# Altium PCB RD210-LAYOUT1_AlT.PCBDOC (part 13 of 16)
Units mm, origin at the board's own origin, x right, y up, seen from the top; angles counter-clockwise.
Board outline 330 x 300 mm, 6 copper layers (TOP, Mid-Layer 1, Mid-Layer 2, Mid-Layer 3, Mid-Layer 4, BOTTOM), stack 1.422 mm thick; 981 components, 463 nets, 2326 pads, 12534 vias.
Unrouted connection lines stored in the file: 6.
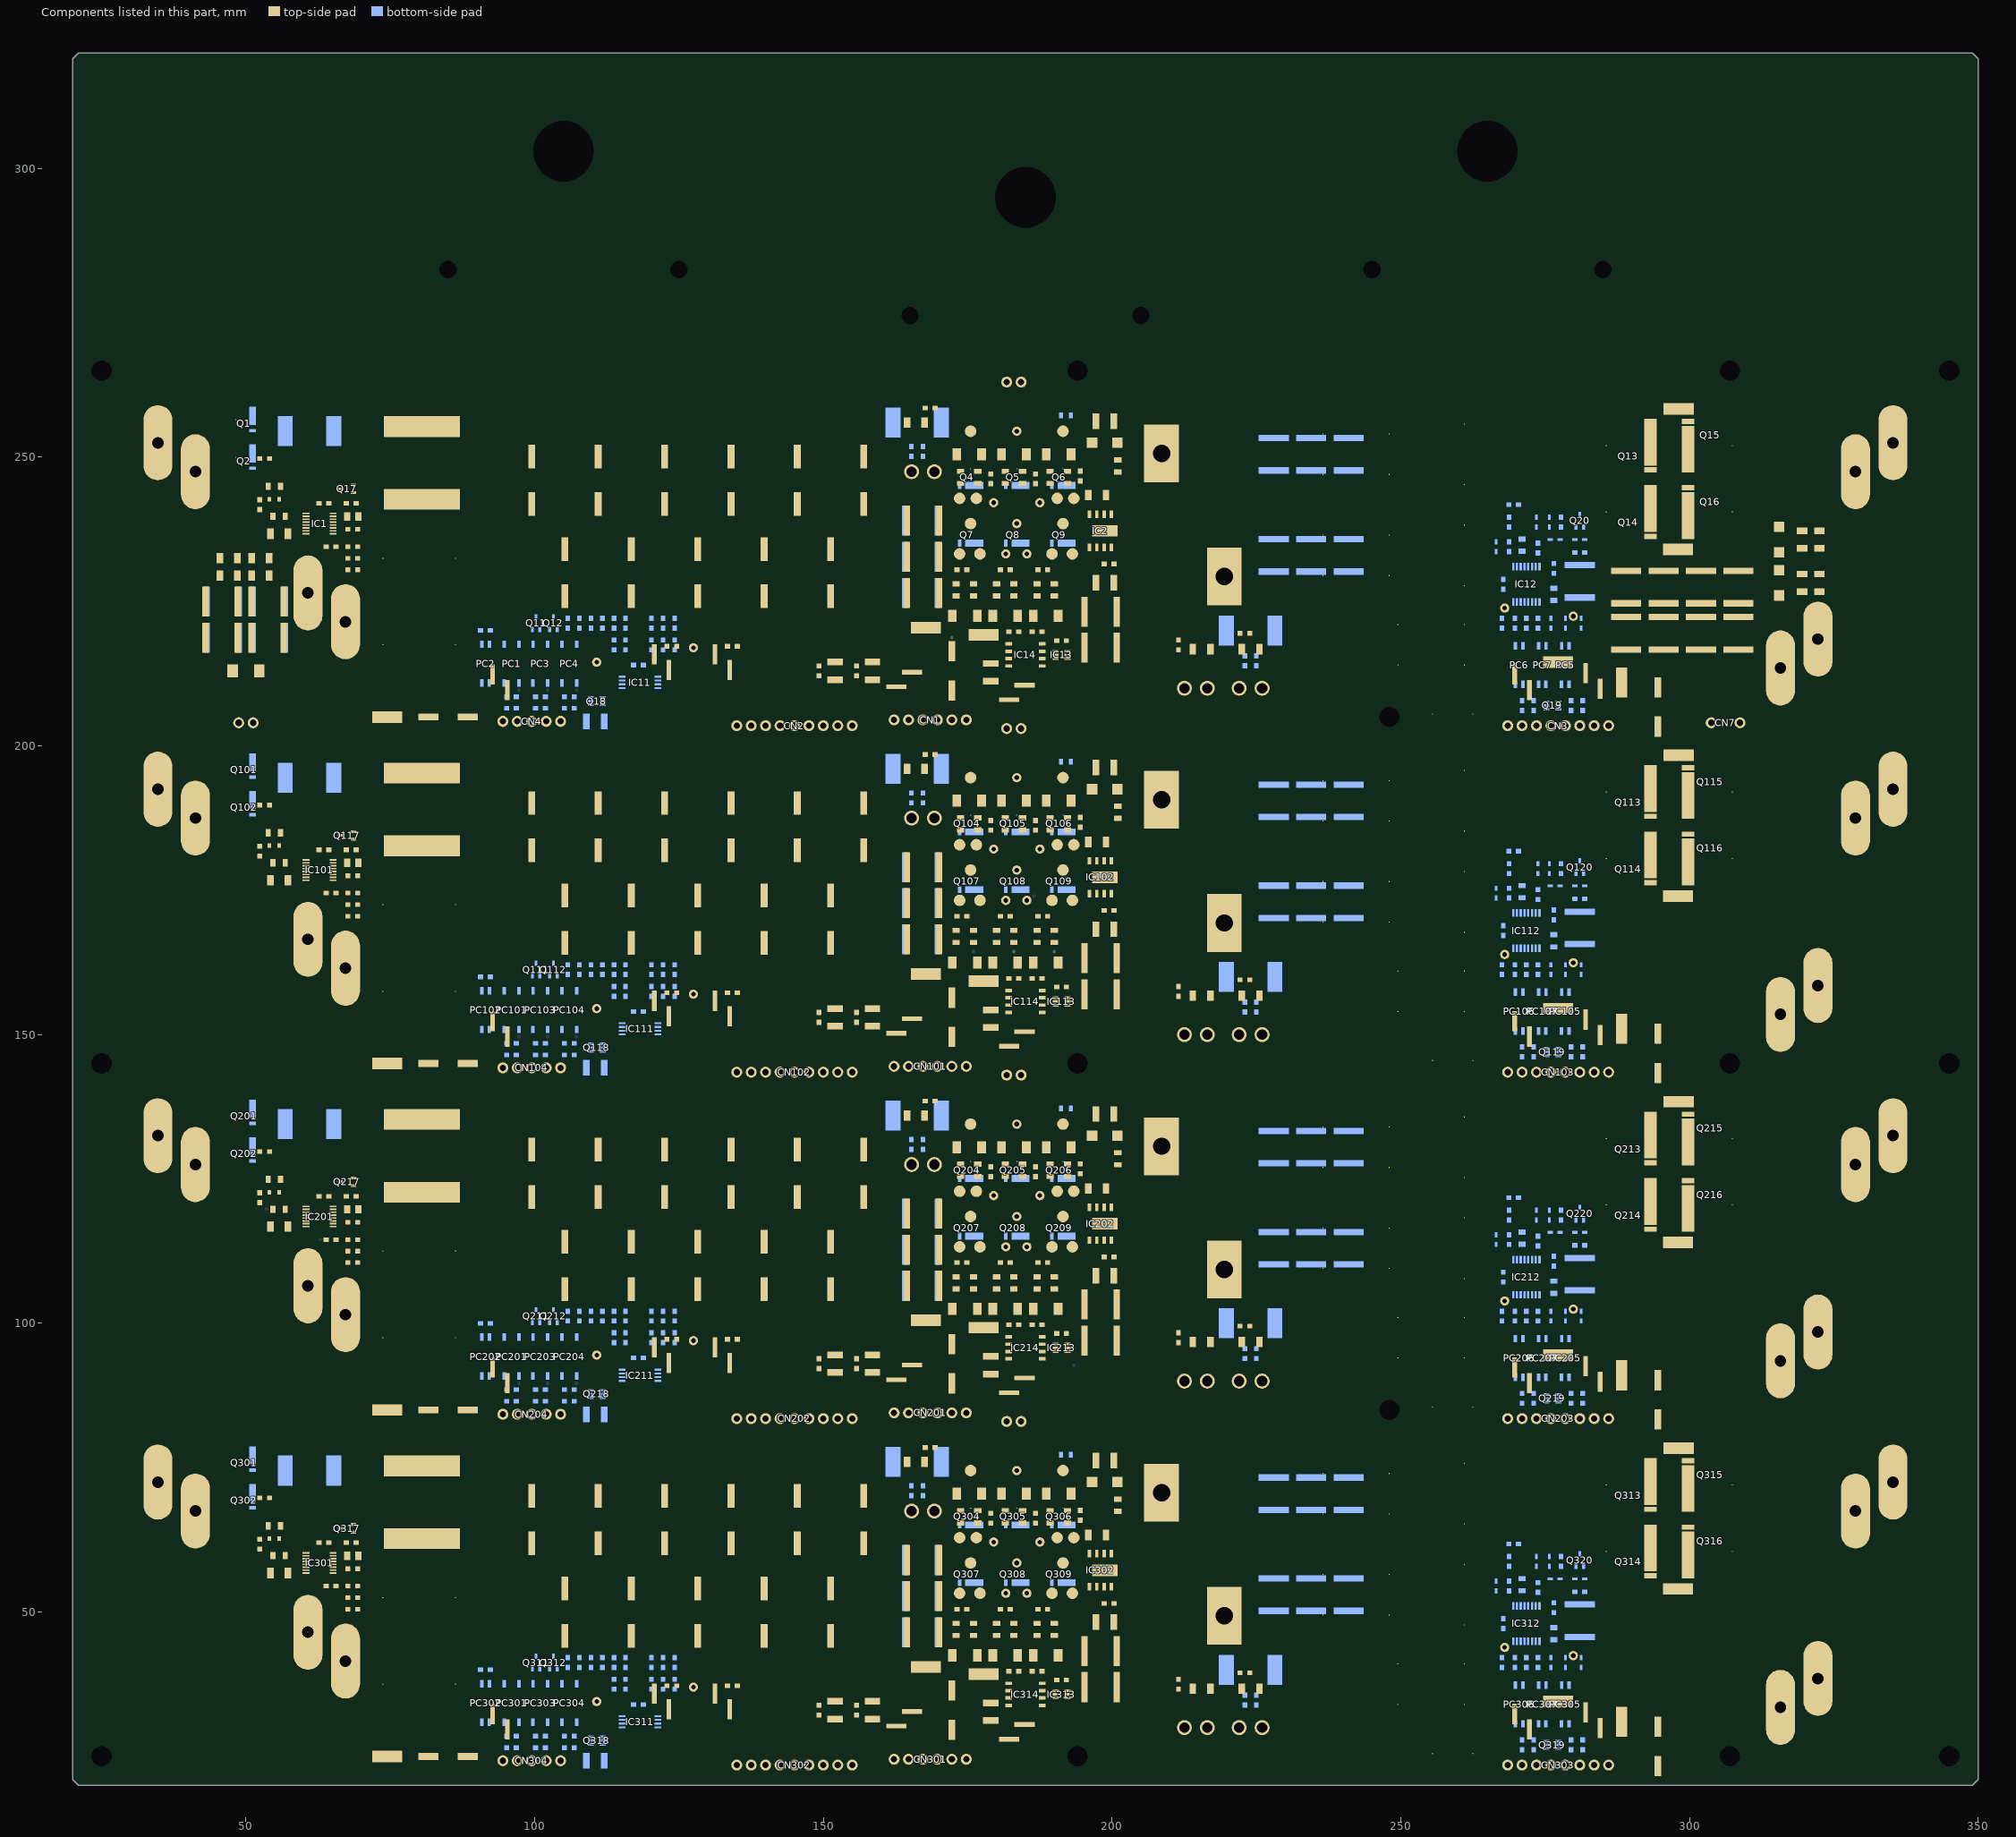
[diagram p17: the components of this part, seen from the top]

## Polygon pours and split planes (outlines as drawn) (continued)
no net on Top Overlay "TOPOVERLAY427" (solid, pour order 0): 191.7,248.8 191.7,252.2 192.65,252.2 192.65,251.7 192,251.7 192,249.3 192.65,249.3 192.65,248.8
no net on Top Overlay "TOPOVERLAY428" (solid, pour order 0): 189.45,220.8 189.45,224.2 190.4,224.2 190.4,223.7 189.75,223.7 189.75,221.3 190.4,221.3 190.4,220.8
no net on Top Overlay "TOPOVERLAY429" (solid, pour order 0): 59.1,241 ccw(c59.4,241) 59.7,241 ccw(c59.4,241)
no net on Top Overlay "TOPOVERLAY430" (solid, pour order 0): 100.325,182.15 102.69,182.15 cw(c99.5,186) 100.325,181.069
no net on Top Overlay "TOPOVERLAY431" (solid, pour order 0): 98.675,181.069 cw(c99.5,186) 96.31,182.15 98.675,182.15
no net on Top Overlay "TOPOVERLAY432" (solid, pour order 0): 111.825,182.15 114.19,182.15 cw(c111,186) 111.825,181.069
no net on Top Overlay "TOPOVERLAY433" (solid, pour order 0): 110.175,181.069 cw(c111,186) 107.81,182.15 110.175,182.15
no net on Top Overlay "TOPOVERLAY434" (solid, pour order 0): 123.325,182.15 125.69,182.15 cw(c122.5,186) 123.325,181.069
no net on Top Overlay "TOPOVERLAY435" (solid, pour order 0): 121.675,181.069 cw(c122.5,186) 119.31,182.15 121.675,182.15
no net on Top Overlay "TOPOVERLAY436" (solid, pour order 0): 134.825,182.15 137.19,182.15 cw(c134,186) 134.825,181.069
no net on Top Overlay "TOPOVERLAY437" (solid, pour order 0): 133.175,181.069 cw(c134,186) 130.81,182.15 133.175,182.15
no net on Top Overlay "TOPOVERLAY438" (solid, pour order 0): 146.325,182.15 148.69,182.15 cw(c145.5,186) 146.325,181.069
no net on Top Overlay "TOPOVERLAY439" (solid, pour order 0): 144.675,181.069 cw(c145.5,186) 142.31,182.15 144.675,182.15
no net on Top Overlay "TOPOVERLAY440" (solid, pour order 0): 157.825,182.15 160.19,182.15 cw(c157,186) 157.825,181.069
no net on Top Overlay "TOPOVERLAY441" (solid, pour order 0): 156.175,181.069 cw(c157,186) 153.81,182.15 156.175,182.15
no net on Top Overlay "TOPOVERLAY442" (solid, pour order 0): 148.06,173.85 cw(c151.25,170) 150.425,174.931 150.425,173.85
no net on Top Overlay "TOPOVERLAY443" (solid, pour order 0): 152.075,173.85 152.075,174.931 cw(c151.25,170) 154.44,173.85
no net on Top Overlay "TOPOVERLAY444" (solid, pour order 0): 136.56,173.85 cw(c139.75,170) 138.925,174.931 138.925,173.85
no net on Top Overlay "TOPOVERLAY445" (solid, pour order 0): 140.575,173.85 140.575,174.931 cw(c139.75,170) 142.94,173.85
no net on Top Overlay "TOPOVERLAY446" (solid, pour order 0): 125.06,173.85 cw(c128.25,170) 127.425,174.931 127.425,173.85
no net on Top Overlay "TOPOVERLAY447" (solid, pour order 0): 129.075,173.85 129.075,174.931 cw(c128.25,170) 131.44,173.85
no net on Top Overlay "TOPOVERLAY448" (solid, pour order 0): 113.56,173.85 cw(c116.75,170) 115.925,174.931 115.925,173.85
no net on Top Overlay "TOPOVERLAY449" (solid, pour order 0): 117.575,173.85 117.575,174.931 cw(c116.75,170) 119.94,173.85
no net on Top Overlay "TOPOVERLAY450" (solid, pour order 0): 102.06,173.85 cw(c105.25,170) 104.425,174.931 104.425,173.85
no net on Top Overlay "TOPOVERLAY451" (solid, pour order 0): 106.075,173.85 106.075,174.931 cw(c105.25,170) 108.44,173.85
no net on Top Overlay "TOPOVERLAY452" (solid, pour order 0): 100.325,122.15 102.69,122.15 cw(c99.5,126) 100.325,121.069
no net on Top Overlay "TOPOVERLAY453" (solid, pour order 0): 98.675,121.069 cw(c99.5,126) 96.31,122.15 98.675,122.15
no net on Top Overlay "TOPOVERLAY454" (solid, pour order 0): 111.825,122.15 114.19,122.15 cw(c111,126) 111.825,121.069
no net on Top Overlay "TOPOVERLAY455" (solid, pour order 0): 110.175,121.069 cw(c111,126) 107.81,122.15 110.175,122.15
no net on Top Overlay "TOPOVERLAY456" (solid, pour order 0): 123.325,122.15 125.69,122.15 cw(c122.5,126) 123.325,121.069
no net on Top Overlay "TOPOVERLAY457" (solid, pour order 0): 121.675,121.069 cw(c122.5,126) 119.31,122.15 121.675,122.15
no net on Top Overlay "TOPOVERLAY458" (solid, pour order 0): 134.825,122.15 137.19,122.15 cw(c134,126) 134.825,121.069
no net on Top Overlay "TOPOVERLAY459" (solid, pour order 0): 133.175,121.069 cw(c134,126) 130.81,122.15 133.175,122.15
no net on Top Overlay "TOPOVERLAY460" (solid, pour order 0): 146.325,122.15 148.69,122.15 cw(c145.5,126) 146.325,121.069
no net on Top Overlay "TOPOVERLAY461" (solid, pour order 0): 144.675,121.069 cw(c145.5,126) 142.31,122.15 144.675,122.15
no net on Top Overlay "TOPOVERLAY462" (solid, pour order 0): 157.825,122.15 160.19,122.15 cw(c157,126) 157.825,121.069
no net on Top Overlay "TOPOVERLAY463" (solid, pour order 0): 156.175,121.069 cw(c157,126) 153.81,122.15 156.175,122.15
no net on Top Overlay "TOPOVERLAY464" (solid, pour order 0): 148.06,113.85 cw(c151.25,110) 150.425,114.931 150.425,113.85
no net on Top Overlay "TOPOVERLAY465" (solid, pour order 0): 152.075,113.85 152.075,114.931 cw(c151.25,110) 154.44,113.85
no net on Top Overlay "TOPOVERLAY466" (solid, pour order 0): 136.56,113.85 cw(c139.75,110) 138.925,114.931 138.925,113.85
no net on Top Overlay "TOPOVERLAY467" (solid, pour order 0): 140.575,113.85 140.575,114.931 cw(c139.75,110) 142.94,113.85
no net on Top Overlay "TOPOVERLAY468" (solid, pour order 0): 125.06,113.85 cw(c128.25,110) 127.425,114.931 127.425,113.85
no net on Top Overlay "TOPOVERLAY469" (solid, pour order 0): 129.075,113.85 129.075,114.931 cw(c128.25,110) 131.44,113.85
no net on Top Overlay "TOPOVERLAY470" (solid, pour order 0): 113.56,113.85 cw(c116.75,110) 115.925,114.931 115.925,113.85
no net on Top Overlay "TOPOVERLAY471" (solid, pour order 0): 117.575,113.85 117.575,114.931 cw(c116.75,110) 119.94,113.85
no net on Top Overlay "TOPOVERLAY472" (solid, pour order 0): 102.06,113.85 cw(c105.25,110) 104.425,114.931 104.425,113.85
no net on Top Overlay "TOPOVERLAY473" (solid, pour order 0): 106.075,113.85 106.075,114.931 cw(c105.25,110) 108.44,113.85
no net on Top Overlay "TOPOVERLAY474" (solid, pour order 0): 100.325,62.15 102.69,62.15 cw(c99.5,66) 100.325,61.069
no net on Top Overlay "TOPOVERLAY475" (solid, pour order 0): 98.675,61.069 cw(c99.5,66) 96.31,62.15 98.675,62.15
no net on Top Overlay "TOPOVERLAY476" (solid, pour order 0): 111.825,62.15 114.19,62.15 cw(c111,66) 111.825,61.069
no net on Top Overlay "TOPOVERLAY477" (solid, pour order 0): 110.175,61.069 cw(c111,66) 107.81,62.15 110.175,62.15
no net on Top Overlay "TOPOVERLAY478" (solid, pour order 0): 123.325,62.15 125.69,62.15 cw(c122.5,66) 123.325,61.069
no net on Top Overlay "TOPOVERLAY479" (solid, pour order 0): 121.675,61.069 cw(c122.5,66) 119.31,62.15 121.675,62.15
no net on Top Overlay "TOPOVERLAY480" (solid, pour order 0): 134.825,62.15 137.19,62.15 cw(c134,66) 134.825,61.069
no net on Top Overlay "TOPOVERLAY481" (solid, pour order 0): 133.175,61.069 cw(c134,66) 130.81,62.15 133.175,62.15
no net on Top Overlay "TOPOVERLAY482" (solid, pour order 0): 146.325,62.15 148.69,62.15 cw(c145.5,66) 146.325,61.069
no net on Top Overlay "TOPOVERLAY483" (solid, pour order 0): 144.675,61.069 cw(c145.5,66) 142.31,62.15 144.675,62.15
no net on Top Overlay "TOPOVERLAY484" (solid, pour order 0): 157.825,62.15 160.19,62.15 cw(c157,66) 157.825,61.069
no net on Top Overlay "TOPOVERLAY485" (solid, pour order 0): 156.175,61.069 cw(c157,66) 153.81,62.15 156.175,62.15
no net on Top Overlay "TOPOVERLAY486" (solid, pour order 0): 148.06,53.85 cw(c151.25,50) 150.425,54.931 150.425,53.85
no net on Top Overlay "TOPOVERLAY487" (solid, pour order 0): 152.075,53.85 152.075,54.931 cw(c151.25,50) 154.44,53.85
no net on Top Overlay "TOPOVERLAY488" (solid, pour order 0): 136.56,53.85 cw(c139.75,50) 138.925,54.931 138.925,53.85
no net on Top Overlay "TOPOVERLAY489" (solid, pour order 0): 140.575,53.85 140.575,54.931 cw(c139.75,50) 142.94,53.85
no net on Top Overlay "TOPOVERLAY490" (solid, pour order 0): 125.06,53.85 cw(c128.25,50) 127.425,54.931 127.425,53.85
no net on Top Overlay "TOPOVERLAY491" (solid, pour order 0): 129.075,53.85 129.075,54.931 cw(c128.25,50) 131.44,53.85
no net on Top Overlay "TOPOVERLAY492" (solid, pour order 0): 113.56,53.85 cw(c116.75,50) 115.925,54.931 115.925,53.85
no net on Top Overlay "TOPOVERLAY493" (solid, pour order 0): 117.575,53.85 117.575,54.931 cw(c116.75,50) 119.94,53.85
no net on Top Overlay "TOPOVERLAY494" (solid, pour order 0): 102.06,53.85 cw(c105.25,50) 104.425,54.931 104.425,53.85
no net on Top Overlay "TOPOVERLAY495" (solid, pour order 0): 106.075,53.85 106.075,54.931 cw(c105.25,50) 108.44,53.85
no net on Top Overlay "TOPOVERLAY496" (solid, pour order 0): 154.75,140.675 ccw(c155,140.675) 155.25,140.675 ccw(c155,140.675)
no net on Top Overlay "TOPOVERLAY497" (solid, pour order 0): 154.75,80.675 ccw(c155,80.675) 155.25,80.675 ccw(c155,80.675)
no net on Top Overlay "TOPOVERLAY498" (solid, pour order 0): 154.75,20.675 ccw(c155,20.675) 155.25,20.675 ccw(c155,20.675)
no net on Top Overlay "TOPOVERLAY499" (solid, pour order 0): 176.2,188.8 176.2,192.2 177.15,192.2 177.15,191.7 176.5,191.7 176.5,189.3 177.15,189.3 177.15,188.8
no net on Top Overlay "TOPOVERLAY500" (solid, pour order 0): 183.95,188.8 183.95,192.2 184.9,192.2 184.9,191.7 184.25,191.7 184.25,189.3 184.9,189.3 184.9,188.8
no net on Top Overlay "TOPOVERLAY501" (solid, pour order 0): 191.7,188.8 191.7,192.2 192.65,192.2 192.65,191.7 192,191.7 192,189.3 192.65,189.3 192.65,188.8
no net on Top Overlay "TOPOVERLAY502" (solid, pour order 0): 175.45,160.8 175.45,164.2 176.4,164.2 176.4,163.7 175.75,163.7 175.75,161.3 176.4,161.3 176.4,160.8
no net on Top Overlay "TOPOVERLAY503" (solid, pour order 0): 182.45,160.8 182.45,164.2 183.4,164.2 183.4,163.7 182.75,163.7 182.75,161.3 183.4,161.3 183.4,160.8
no net on Top Overlay "TOPOVERLAY504" (solid, pour order 0): 189.45,160.8 189.45,164.2 190.4,164.2 190.4,163.7 189.75,163.7 189.75,161.3 190.4,161.3 190.4,160.8
no net on Top Overlay "TOPOVERLAY505" (solid, pour order 0): 176.2,128.8 176.2,132.2 177.15,132.2 177.15,131.7 176.5,131.7 176.5,129.3 177.15,129.3 177.15,128.8
no net on Top Overlay "TOPOVERLAY506" (solid, pour order 0): 183.95,128.8 183.95,132.2 184.9,132.2 184.9,131.7 184.25,131.7 184.25,129.3 184.9,129.3 184.9,128.8
no net on Top Overlay "TOPOVERLAY507" (solid, pour order 0): 191.7,128.8 191.7,132.2 192.65,132.2 192.65,131.7 192,131.7 192,129.3 192.65,129.3 192.65,128.8
no net on Top Overlay "TOPOVERLAY508" (solid, pour order 0): 175.45,100.8 175.45,104.2 176.4,104.2 176.4,103.7 175.75,103.7 175.75,101.3 176.4,101.3 176.4,100.8
no net on Top Overlay "TOPOVERLAY509" (solid, pour order 0): 182.45,100.8 182.45,104.2 183.4,104.2 183.4,103.7 182.75,103.7 182.75,101.3 183.4,101.3 183.4,100.8
no net on Top Overlay "TOPOVERLAY510" (solid, pour order 0): 189.45,100.8 189.45,104.2 190.4,104.2 190.4,103.7 189.75,103.7 189.75,101.3 190.4,101.3 190.4,100.8
no net on Top Overlay "TOPOVERLAY511" (solid, pour order 0): 176.2,68.8 176.2,72.2 177.15,72.2 177.15,71.7 176.5,71.7 176.5,69.3 177.15,69.3 177.15,68.8
no net on Top Overlay "TOPOVERLAY512" (solid, pour order 0): 183.95,68.8 183.95,72.2 184.9,72.2 184.9,71.7 184.25,71.7 184.25,69.3 184.9,69.3 184.9,68.8
no net on Top Overlay "TOPOVERLAY513" (solid, pour order 0): 191.7,68.8 191.7,72.2 192.65,72.2 192.65,71.7 192,71.7 192,69.3 192.65,69.3 192.65,68.8
no net on Top Overlay "TOPOVERLAY514" (solid, pour order 0): 175.45,40.8 175.45,44.2 176.4,44.2 176.4,43.7 175.75,43.7 175.75,41.3 176.4,41.3 176.4,40.8
no net on Top Overlay "TOPOVERLAY515" (solid, pour order 0): 182.45,40.8 182.45,44.2 183.4,44.2 183.4,43.7 182.75,43.7 182.75,41.3 183.4,41.3 183.4,40.8
no net on Top Overlay "TOPOVERLAY516" (solid, pour order 0): 189.45,40.8 189.45,44.2 190.4,44.2 190.4,43.7 189.75,43.7 189.75,41.3 190.4,41.3 190.4,40.8
no net on Top Overlay "TOPOVERLAY517" (solid, pour order 0): 59.1,180.7 ccw(c59.4,180.7) 59.7,180.7 ccw(c59.4,180.7)
no net on Top Overlay "TOPOVERLAY518" (solid, pour order 0): 59.1,120.7 ccw(c59.4,120.7) 59.7,120.7 ccw(c59.4,120.7)
no net on Top Overlay "TOPOVERLAY519" (solid, pour order 0): 59.1,60.7 ccw(c59.4,60.7) 59.7,60.7 ccw(c59.4,60.7)
no net on Top Overlay "TOPOVERLAY520" (solid, pour order 0): 51,201.15 ccw(c51.25,201.15) 51.5,201.15 ccw(c51.25,201.15)
no net on Top Overlay "TOPOVERLAY521" (solid, pour order 0): 188.95,216.4 ccw(c189.2,216.4) 189.45,216.4 ccw(c189.2,216.4)
no net on Top Overlay "TOPOVERLAY522" (solid, pour order 0): 180.75,217.655 ccw(c181,217.655) 181.25,217.655 ccw(c181,217.655)
no net on Top Overlay "TOPOVERLAY523" (solid, pour order 0): 188.95,156.4 ccw(c189.2,156.4) 189.45,156.4 ccw(c189.2,156.4)
no net on Top Overlay "TOPOVERLAY524" (solid, pour order 0): 180.75,157.655 ccw(c181,157.655) 181.25,157.655 ccw(c181,157.655)
no net on Top Overlay "TOPOVERLAY525" (solid, pour order 0): 188.95,96.4 ccw(c189.2,96.4) 189.45,96.4 ccw(c189.2,96.4)
no net on Top Overlay "TOPOVERLAY526" (solid, pour order 0): 180.75,97.655 ccw(c181,97.655) 181.25,97.655 ccw(c181,97.655)
no net on Top Overlay "TOPOVERLAY527" (solid, pour order 0): 188.95,36.4 ccw(c189.2,36.4) 189.45,36.4 ccw(c189.2,36.4)
no net on Top Overlay "TOPOVERLAY528" (solid, pour order 0): 180.75,37.655 ccw(c181,37.655) 181.25,37.655 ccw(c181,37.655)
no net on Top Overlay "TOPOVERLAY529" (solid, pour order 0): 69.3,243.85 ccw(c69.55,243.85) 69.8,243.85 ccw(c69.55,243.85)
no net on Top Overlay "TOPOVERLAY530" (solid, pour order 0): 69.3,183.85 ccw(c69.55,183.85) 69.8,183.85 ccw(c69.55,183.85)
no net on Top Overlay "TOPOVERLAY531" (solid, pour order 0): 69.3,123.85 ccw(c69.55,123.85) 69.8,123.85 ccw(c69.55,123.85)
no net on Top Overlay "TOPOVERLAY532" (solid, pour order 0): 69.3,63.85 ccw(c69.55,63.85) 69.8,63.85 ccw(c69.55,63.85)
no net on Top Overlay "TOPOVERLAY533" (solid, pour order 0): 94.25,27.1 ccw(c94.5,27.1) 94.75,27.1 ccw(c94.5,27.1)
no net on Top Overlay "TOPOVERLAY534" (solid, pour order 0): 94.25,207.1 ccw(c94.5,207.1) 94.75,207.1 ccw(c94.5,207.1)
no net on Top Overlay "TOPOVERLAY535" (solid, pour order 0): 94.25,147.1 ccw(c94.5,147.1) 94.75,147.1 ccw(c94.5,147.1)
no net on Top Overlay "TOPOVERLAY536" (solid, pour order 0): 94.25,87.1 ccw(c94.5,87.1) 94.75,87.1 ccw(c94.5,87.1)
no net on Top Overlay "TOPOVERLAY537" (solid, pour order 0): 196.6,250.7 196.6,251.45 197.6,251.45 197.6,253.55 196.6,253.55 196.6,254.3 197.9,254.3 197.9,250.7
no net on Top Overlay "TOPOVERLAY538" (solid, pour order 0): 196.6,190.7 196.6,191.45 197.6,191.45 197.6,193.55 196.6,193.55 196.6,194.3 197.9,194.3 197.9,190.7
no net on Top Overlay "TOPOVERLAY539" (solid, pour order 0): 196.6,130.7 196.6,131.45 197.6,131.45 197.6,133.55 196.6,133.55 196.6,134.3 197.9,134.3 197.9,130.7
no net on Top Overlay "TOPOVERLAY540" (solid, pour order 0): 196.6,70.7 196.6,71.45 197.6,71.45 197.6,73.55 196.6,73.55 196.6,74.3 197.9,74.3 197.9,70.7
no net on Top Overlay "TOPOVERLAY541" (solid, pour order 0): 82.15,202.193 cw(c85,205) 81.076,204.225 82.15,204.225
no net on Top Overlay "TOPOVERLAY542" (solid, pour order 0): 81.086,205.825 cw(c85,205) 82.15,207.807 82.15,205.825
no net on Top Overlay "TOPOVERLAY543" (solid, pour order 0): 82.15,142.193 cw(c85,145) 81.076,144.225 82.15,144.225
no net on Top Overlay "TOPOVERLAY544" (solid, pour order 0): 81.086,145.825 cw(c85,145) 82.15,147.807 82.15,145.825
no net on Top Overlay "TOPOVERLAY545" (solid, pour order 0): 169.443,155.85 cw(c172.25,153) 171.475,156.924 171.475,155.85
no net on Top Overlay "TOPOVERLAY546" (solid, pour order 0): 173.075,155.85 173.075,156.914 cw(c172.25,153) 175.057,155.85
no net on Top Overlay "TOPOVERLAY547" (solid, pour order 0): 82.15,82.193 cw(c85,85) 81.076,84.225 82.15,84.225
no net on Top Overlay "TOPOVERLAY548" (solid, pour order 0): 81.086,85.825 cw(c85,85) 82.15,87.807 82.15,85.825
no net on Top Overlay "TOPOVERLAY549" (solid, pour order 0): 169.443,95.85 cw(c172.25,93) 171.475,96.924 171.475,95.85
no net on Top Overlay "TOPOVERLAY550" (solid, pour order 0): 173.075,95.85 173.075,96.914 cw(c172.25,93) 175.057,95.85
no net on Top Overlay "TOPOVERLAY551" (solid, pour order 0): 82.15,22.193 cw(c85,25) 81.076,24.225 82.15,24.225
no net on Top Overlay "TOPOVERLAY552" (solid, pour order 0): 81.086,25.825 cw(c85,25) 82.15,27.807 82.15,25.825
no net on Top Overlay "TOPOVERLAY553" (solid, pour order 0): 169.443,35.85 cw(c172.25,33) 171.475,36.924 171.475,35.85
no net on Top Overlay "TOPOVERLAY554" (solid, pour order 0): 173.075,35.85 173.075,36.914 cw(c172.25,33) 175.057,35.85
no net on Top Overlay "TOPOVERLAY555" (solid, pour order 0): 291.693,209.6 cw(c294.5,206.75) 293.725,210.674 293.725,209.6
no net on Top Overlay "TOPOVERLAY556" (solid, pour order 0): 295.325,209.6 295.325,210.664 cw(c294.5,206.75) 297.307,209.6
no net on Top Overlay "TOPOVERLAY557" (solid, pour order 0): 169.443,215.85 cw(c172.25,213) 171.475,216.924 171.475,215.85
no net on Top Overlay "TOPOVERLAY558" (solid, pour order 0): 173.075,215.85 173.075,216.914 cw(c172.25,213) 175.057,215.85
no net on Top Overlay "TOPOVERLAY559" (solid, pour order 0): 162,207.35 ccw(c162.25,207.35) 162.5,207.35 ccw(c162.25,207.35)
no net on Top Overlay "TOPOVERLAY560" (solid, pour order 0): 285.75,200.675 ccw(c286,200.675) 286.25,200.675 ccw(c286,200.675)
no net on Top Overlay "TOPOVERLAY561" (solid, pour order 0): 291.693,149.6 cw(c294.5,146.75) 293.725,150.674 293.725,149.6
no net on Top Overlay "TOPOVERLAY562" (solid, pour order 0): 295.325,149.6 295.325,150.664 cw(c294.5,146.75) 297.307,149.6
no net on Top Overlay "TOPOVERLAY563" (solid, pour order 0): 291.693,89.6 cw(c294.5,86.75) 293.725,90.674 293.725,89.6
no net on Top Overlay "TOPOVERLAY564" (solid, pour order 0): 295.325,89.6 295.325,90.664 cw(c294.5,86.75) 297.307,89.6
no net on Top Overlay "TOPOVERLAY565" (solid, pour order 0): 291.693,29.6 cw(c294.5,26.75) 293.725,30.674 293.725,29.6
no net on Top Overlay "TOPOVERLAY566" (solid, pour order 0): 295.325,29.6 295.325,30.664 cw(c294.5,26.75) 297.307,29.6
no net on Top Overlay "TOPOVERLAY567" (solid, pour order 0): 162,27.35 ccw(c162.25,27.35) 162.5,27.35 ccw(c162.25,27.35)
no net on Top Overlay "TOPOVERLAY568" (solid, pour order 0): 162,147.35 ccw(c162.25,147.35) 162.5,147.35 ccw(c162.25,147.35)
no net on Top Overlay "TOPOVERLAY569" (solid, pour order 0): 162,87.35 ccw(c162.25,87.35) 162.5,87.35 ccw(c162.25,87.35)
no net on Top Overlay "TOPOVERLAY570" (solid, pour order 0): 285.75,140.675 ccw(c286,140.675) 286.25,140.675 ccw(c286,140.675)
no net on Top Overlay "TOPOVERLAY571" (solid, pour order 0): 285.75,80.675 ccw(c286,80.675) 286.25,80.675 ccw(c286,80.675)
no net on Top Overlay "TOPOVERLAY572" (solid, pour order 0): 285.75,20.675 ccw(c286,20.675) 286.25,20.675 ccw(c286,20.675)
no net on Top Overlay "TOPOVERLAY573" (solid, pour order 0): 236.375,53 ccw(c236.5,53) 236.625,53 ccw(c236.5,53)
no net on Top Overlay "TOPOVERLAY574" (solid, pour order 0): 247.875,53 ccw(c248,53) 248.125,53 ccw(c248,53)
no net on Top Overlay "TOPOVERLAY575" (solid, pour order 0): 249.375,37.5 ccw(c249.5,37.5) 249.625,37.5 ccw(c249.5,37.5)
no net on Top Overlay "TOPOVERLAY576" (solid, pour order 0): 260.875,37.5 ccw(c261,37.5) 261.125,37.5 ccw(c261,37.5)
no net on Top Overlay "TOPOVERLAY577" (solid, pour order 0): 200.3,241.15 ccw(c200.6,241.15) 200.9,241.15 ccw(c200.6,241.15)
no net on Top Overlay "TOPOVERLAY578" (solid, pour order 0): 200.3,181.15 ccw(c200.6,181.15) 200.9,181.15 ccw(c200.6,181.15)
no net on Top Overlay "TOPOVERLAY579" (solid, pour order 0): 200.3,121.15 ccw(c200.6,121.15) 200.9,121.15 ccw(c200.6,121.15)
no net on Top Overlay "TOPOVERLAY580" (solid, pour order 0): 200.3,61.15 ccw(c200.6,61.15) 200.9,61.15 ccw(c200.6,61.15)
no net on Top Overlay "TOPOVERLAY581" (solid, pour order 0): 165.02,242.225 ccw(c165.27,242.225) 165.52,242.225 ccw(c165.27,242.225)
no net on Top Overlay "TOPOVERLAY582" (solid, pour order 0): 225.73,215.275 ccw(c225.98,215.275) 226.23,215.275 ccw(c225.98,215.275)
no net on Top Overlay "TOPOVERLAY583" (solid, pour order 0): 216.23,215.275 ccw(c216.48,215.275) 216.73,215.275 ccw(c216.48,215.275)
no net on Top Overlay "TOPOVERLAY584" (solid, pour order 0): 165.02,182.225 ccw(c165.27,182.225) 165.52,182.225 ccw(c165.27,182.225)
no net on Top Overlay "TOPOVERLAY585" (solid, pour order 0): 225.73,155.275 ccw(c225.98,155.275) 226.23,155.275 ccw(c225.98,155.275)
no net on Top Overlay "TOPOVERLAY586" (solid, pour order 0): 216.23,155.275 ccw(c216.48,155.275) 216.73,155.275 ccw(c216.48,155.275)
no net on Top Overlay "TOPOVERLAY587" (solid, pour order 0): 165.02,122.225 ccw(c165.27,122.225) 165.52,122.225 ccw(c165.27,122.225)
no net on Top Overlay "TOPOVERLAY588" (solid, pour order 0): 225.73,95.275 ccw(c225.98,95.275) 226.23,95.275 ccw(c225.98,95.275)
no net on Top Overlay "TOPOVERLAY589" (solid, pour order 0): 216.23,95.275 ccw(c216.48,95.275) 216.73,95.275 ccw(c216.48,95.275)
no net on Top Overlay "TOPOVERLAY590" (solid, pour order 0): 165.02,62.225 ccw(c165.27,62.225) 165.52,62.225 ccw(c165.27,62.225)
no net on Top Overlay "TOPOVERLAY591" (solid, pour order 0): 225.73,35.275 ccw(c225.98,35.275) 226.23,35.275 ccw(c225.98,35.275)
no net on Top Overlay "TOPOVERLAY592" (solid, pour order 0): 216.23,35.275 ccw(c216.48,35.275) 216.73,35.275 ccw(c216.48,35.275)
no net on Top Overlay "TOPOVERLAY593" (solid, pour order 0): 313.7,233.6 313.7,234.9 317.3,234.9 317.3,233.6 316.55,233.6 316.55,234.6 314.45,234.6 314.45,233.6
no net on Top Overlay "TOPOVERLAY594" (solid, pour order 0): 313.7,229.1 313.7,230.4 314.45,230.4 314.45,229.4 316.55,229.4 316.55,230.4 317.3,230.4 317.3,229.1
no net on Top Overlay "TOPOVERLAY595" (solid, pour order 0): 261.85,204.675 262.914,204.675 cw(c259,205.5) 261.85,202.693
no net on Top Overlay "TOPOVERLAY596" (solid, pour order 0): 261.85,206.325 261.85,208.307 cw(c259,205.5) 262.914,206.325
no net on Top Overlay "TOPOVERLAY597" (solid, pour order 0): 261.85,144.675 262.914,144.675 cw(c259,145.5) 261.85,142.693
no net on Top Overlay "TOPOVERLAY598" (solid, pour order 0): 261.85,146.325 261.85,148.307 cw(c259,145.5) 262.914,146.325
no net on Top Overlay "TOPOVERLAY599" (solid, pour order 0): 261.85,84.675 262.914,84.675 cw(c259,85.5) 261.85,82.693
no net on Top Overlay "TOPOVERLAY600" (solid, pour order 0): 261.85,86.325 261.85,88.307 cw(c259,85.5) 262.914,86.325
no net on Top Overlay "TOPOVERLAY601" (solid, pour order 0): 261.85,24.675 262.914,24.675 cw(c259,25.5) 261.85,22.693
no net on Top Overlay "TOPOVERLAY602" (solid, pour order 0): 261.85,26.325 261.85,28.307 cw(c259,25.5) 262.914,26.325
no net on Top Overlay "TOPOVERLAY603" (solid, pour order 0): 184.05,205.7 ccw(c184.25,205.7) 184.45,205.7 ccw(c184.25,205.7)
no net on Top Overlay "TOPOVERLAY604" (solid, pour order 0): 184.05,265.7 ccw(c184.25,265.7) 184.45,265.7 ccw(c184.25,265.7)
no net on Top Overlay "TOPOVERLAY605" (solid, pour order 0): 184.05,145.7 ccw(c184.25,145.7) 184.45,145.7 ccw(c184.25,145.7)
no net on Top Overlay "TOPOVERLAY606" (solid, pour order 0): 184.05,85.7 ccw(c184.25,85.7) 184.45,85.7 ccw(c184.25,85.7)
no net on Top Overlay "TOPOVERLAY607" (solid, pour order 0): 237.275,247.65 239.307,247.65 cw(c236.5,250.5) 237.275,246.576
no net on Top Overlay "TOPOVERLAY608" (solid, pour order 0): 235.725,246.576 cw(c236.5,250.5) 233.697,247.646 233.693,247.65 235.725,247.65
no net on Top Overlay "TOPOVERLAY609" (solid, pour order 0): 248.775,247.65 250.807,247.65 cw(c248,250.5) 248.775,246.576
no net on Top Overlay "TOPOVERLAY610" (solid, pour order 0): 247.225,246.576 cw(c248,250.5) 245.197,247.646 245.193,247.65 247.225,247.65
no net on Top Overlay "TOPOVERLAY611" (solid, pour order 0): 233.693,235.85 cw(c236.5,233) 235.725,236.924 235.725,235.85
no net on Top Overlay "TOPOVERLAY612" (solid, pour order 0): 237.275,235.85 237.275,236.924 cw(c236.5,233) 239.303,235.854 239.307,235.85
no net on Top Overlay "TOPOVERLAY613" (solid, pour order 0): 245.193,235.85 cw(c248,233) 247.225,236.924 247.225,235.85
no net on Top Overlay "TOPOVERLAY614" (solid, pour order 0): 248.775,235.85 248.775,236.924 cw(c248,233) 250.803,235.854 250.807,235.85
no net on Top Overlay "TOPOVERLAY615" (solid, pour order 0): 250.275,214.65 252.307,214.65 cw(c249.5,217.5) 250.275,213.576
no net on Top Overlay "TOPOVERLAY616" (solid, pour order 0): 248.725,213.576 cw(c249.5,217.5) 246.697,214.646 246.693,214.65 248.725,214.65
no net on Top Overlay "TOPOVERLAY617" (solid, pour order 0): 261.775,214.65 263.807,214.65 cw(c261,217.5) 261.775,213.576
no net on Top Overlay "TOPOVERLAY618" (solid, pour order 0): 260.225,213.576 cw(c261,217.5) 258.197,214.646 258.193,214.65 260.225,214.65
no net on Top Overlay "TOPOVERLAY619" (solid, pour order 0): 237.275,187.65 239.307,187.65 cw(c236.5,190.5) 237.275,186.576
no net on Top Overlay "TOPOVERLAY620" (solid, pour order 0): 235.725,186.576 cw(c236.5,190.5) 233.697,187.646 233.693,187.65 235.725,187.65
no net on Top Overlay "TOPOVERLAY621" (solid, pour order 0): 248.775,187.65 250.807,187.65 cw(c248,190.5) 248.775,186.576
no net on Top Overlay "TOPOVERLAY622" (solid, pour order 0): 247.225,186.576 cw(c248,190.5) 245.197,187.646 245.193,187.65 247.225,187.65
no net on Top Overlay "TOPOVERLAY623" (solid, pour order 0): 250.275,154.65 252.307,154.65 cw(c249.5,157.5) 250.275,153.576
no net on Top Overlay "TOPOVERLAY624" (solid, pour order 0): 248.725,153.576 cw(c249.5,157.5) 246.697,154.646 246.693,154.65 248.725,154.65
no net on Top Overlay "TOPOVERLAY625" (solid, pour order 0): 261.775,154.65 263.807,154.65 cw(c261,157.5) 261.775,153.576
no net on Top Overlay "TOPOVERLAY626" (solid, pour order 0): 260.225,153.576 cw(c261,157.5) 258.197,154.646 258.193,154.65 260.225,154.65
no net on Top Overlay "TOPOVERLAY627" (solid, pour order 0): 237.275,127.65 239.307,127.65 cw(c236.5,130.5) 237.275,126.576
no net on Top Overlay "TOPOVERLAY628" (solid, pour order 0): 235.725,126.576 cw(c236.5,130.5) 233.697,127.646 233.693,127.65 235.725,127.65
no net on Top Overlay "TOPOVERLAY629" (solid, pour order 0): 248.775,127.65 250.807,127.65 cw(c248,130.5) 248.775,126.576
no net on Top Overlay "TOPOVERLAY630" (solid, pour order 0): 247.225,126.576 cw(c248,130.5) 245.197,127.646 245.193,127.65 247.225,127.65
no net on Top Overlay "TOPOVERLAY631" (solid, pour order 0): 261.775,94.65 263.807,94.65 cw(c261,97.5) 261.775,93.576
no net on Top Overlay "TOPOVERLAY632" (solid, pour order 0): 260.225,93.576 cw(c261,97.5) 258.197,94.646 258.193,94.65 260.225,94.65
no net on Top Overlay "TOPOVERLAY633" (solid, pour order 0): 250.275,94.65 252.307,94.65 cw(c249.5,97.5) 250.275,93.576
no net on Top Overlay "TOPOVERLAY634" (solid, pour order 0): 248.725,93.576 cw(c249.5,97.5) 246.697,94.646 246.693,94.65 248.725,94.65
no net on Top Overlay "TOPOVERLAY635" (solid, pour order 0): 237.275,67.65 239.307,67.65 cw(c236.5,70.5) 237.275,66.576
no net on Top Overlay "TOPOVERLAY636" (solid, pour order 0): 235.725,66.576 cw(c236.5,70.5) 233.697,67.646 233.693,67.65 235.725,67.65
no net on Top Overlay "TOPOVERLAY637" (solid, pour order 0): 248.775,67.65 250.807,67.65 cw(c248,70.5) 248.775,66.576
no net on Top Overlay "TOPOVERLAY638" (solid, pour order 0): 247.225,66.576 cw(c248,70.5) 245.197,67.646 245.193,67.65 247.225,67.65
no net on Top Overlay "TOPOVERLAY639" (solid, pour order 0): 233.693,55.85 cw(c236.5,53) 235.725,56.924 235.725,55.85
no net on Top Overlay "TOPOVERLAY640" (solid, pour order 0): 237.275,55.85 237.275,56.924 cw(c236.5,53) 239.303,55.854 239.307,55.85
no net on Top Overlay "TOPOVERLAY641" (solid, pour order 0): 245.193,55.85 cw(c248,53) 247.225,56.924 247.225,55.85
no net on Top Overlay "TOPOVERLAY642" (solid, pour order 0): 248.775,55.85 248.775,56.924 cw(c248,53) 250.803,55.854 250.807,55.85
no net on Top Overlay "TOPOVERLAY643" (solid, pour order 0): 250.275,34.65 252.307,34.65 cw(c249.5,37.5) 250.275,33.576
no net on Top Overlay "TOPOVERLAY644" (solid, pour order 0): 248.725,33.576 cw(c249.5,37.5) 246.697,34.646 246.693,34.65 248.725,34.65
no net on Top Overlay "TOPOVERLAY645" (solid, pour order 0): 261.775,34.65 263.807,34.65 cw(c261,37.5) 261.775,33.576
no net on Top Overlay "TOPOVERLAY646" (solid, pour order 0): 260.225,33.576 cw(c261,37.5) 258.197,34.646 258.193,34.65 260.225,34.65
no net on Top Overlay "TOPOVERLAY647" (solid, pour order 0): 245.193,175.85 cw(c248,173) 247.225,176.924 247.225,175.85
no net on Top Overlay "TOPOVERLAY648" (solid, pour order 0): 248.775,175.85 248.775,176.924 cw(c248,173) 250.803,175.854 250.807,175.85
no net on Top Overlay "TOPOVERLAY649" (solid, pour order 0): 233.693,175.85 cw(c236.5,173) 235.725,176.924 235.725,175.85
no net on Top Overlay "TOPOVERLAY650" (solid, pour order 0): 237.275,175.85 237.275,176.924 cw(c236.5,173) 239.303,175.854 239.307,175.85
no net on Top Overlay "TOPOVERLAY651" (solid, pour order 0): 233.693,115.85 cw(c236.5,113) 235.725,116.924 235.725,115.85
no net on Top Overlay "TOPOVERLAY652" (solid, pour order 0): 237.275,115.85 237.275,116.924 cw(c236.5,113) 239.303,115.854 239.307,115.85
no net on Top Overlay "TOPOVERLAY653" (solid, pour order 0): 245.193,115.85 cw(c248,113) 247.225,116.924 247.225,115.85
no net on Top Overlay "TOPOVERLAY654" (solid, pour order 0): 248.775,115.85 248.775,116.924 cw(c248,113) 250.803,115.854 250.807,115.85
no net on Top Overlay "TOPOVERLAY655" (solid, pour order 0): 308.5,201.15 ccw(c308.75,201.15) 309,201.15 ccw(c308.75,201.15)
no net on Top Overlay "TOPOVERLAY656" (solid, pour order 0): 76.25,212.5 cw(c80,217.5) 74.981,213.775 76.25,213.775
no net on Top Overlay "TOPOVERLAY657" (solid, pour order 0): 74.981,221.225 cw(c80,217.5) 76.25,222.5 76.25,221.225
no net on Top Overlay "TOPOVERLAY658" (solid, pour order 0): 76.25,227.5 cw(c80,232.5) 74.981,228.775 76.25,228.775
no net on Top Overlay "TOPOVERLAY659" (solid, pour order 0): 74.981,236.225 cw(c80,232.5) 76.25,237.5 76.25,236.225
no net on Top Overlay "TOPOVERLAY660" (solid, pour order 0): 261.975,245.375 264.577,245.375 cw(c261,250.5) 261.975,244.326
no net on Top Overlay "TOPOVERLAY661" (solid, pour order 0): 260.025,244.326 cw(c261,250.5) 257.423,245.375 260.025,245.375
no net on Top Overlay "TOPOVERLAY662" (solid, pour order 0): 257.423,238.125 cw(c261,233) 260.025,239.173 260.025,238.125
no net on Top Overlay "TOPOVERLAY663" (solid, pour order 0): 261.975,238.125 261.975,239.173 cw(c261,233) 264.577,238.125
no net on Top Overlay "TOPOVERLAY664" (solid, pour order 0): 76.25,167.5 cw(c80,172.5) 74.981,168.775 76.25,168.775
no net on Top Overlay "TOPOVERLAY665" (solid, pour order 0): 74.981,176.225 cw(c80,172.5) 76.25,177.5 76.25,176.225
no net on Top Overlay "TOPOVERLAY666" (solid, pour order 0): 76.25,152.5 cw(c80,157.5) 74.981,153.775 76.25,153.775
no net on Top Overlay "TOPOVERLAY667" (solid, pour order 0): 74.981,161.225 cw(c80,157.5) 76.25,162.5 76.25,161.225
no net on Top Overlay "TOPOVERLAY668" (solid, pour order 0): 76.25,107.5 cw(c80,112.5) 74.981,108.775 76.25,108.775
no net on Top Overlay "TOPOVERLAY669" (solid, pour order 0): 74.981,116.225 cw(c80,112.5) 76.25,117.5 76.25,116.225
no net on Top Overlay "TOPOVERLAY670" (solid, pour order 0): 76.25,92.5 cw(c80,97.5) 74.981,93.775 76.25,93.775
no net on Top Overlay "TOPOVERLAY671" (solid, pour order 0): 74.981,101.225 cw(c80,97.5) 76.25,102.5 76.25,101.225
no net on Top Overlay "TOPOVERLAY672" (solid, pour order 0): 76.25,47.5 cw(c80,52.5) 74.981,48.775 76.25,48.775
no net on Top Overlay "TOPOVERLAY673" (solid, pour order 0): 74.981,56.225 cw(c80,52.5) 76.25,57.5 76.25,56.225
no net on Top Overlay "TOPOVERLAY674" (solid, pour order 0): 76.25,32.5 cw(c80,37.5) 74.981,33.775 76.25,33.775
no net on Top Overlay "TOPOVERLAY675" (solid, pour order 0): 74.981,41.225 cw(c80,37.5) 76.25,42.5 76.25,41.225
no net on Top Overlay "TOPOVERLAY676" (solid, pour order 0): 261.975,65.375 264.577,65.375 cw(c261,70.5) 261.975,64.327
no net on Top Overlay "TOPOVERLAY677" (solid, pour order 0): 260.025,64.327 cw(c261,70.5) 257.423,65.375 260.025,65.375
no net on Top Overlay "TOPOVERLAY678" (solid, pour order 0): 257.423,58.125 cw(c261,53) 260.025,59.173 260.025,58.125
no net on Top Overlay "TOPOVERLAY679" (solid, pour order 0): 261.975,58.125 261.975,59.173 cw(c261,53) 264.577,58.125
no net on Top Overlay "TOPOVERLAY680" (solid, pour order 0): 261.975,185.375 264.577,185.375 cw(c261,190.5) 261.975,184.327
no net on Top Overlay "TOPOVERLAY681" (solid, pour order 0): 260.025,184.327 cw(c261,190.5) 257.423,185.375 260.025,185.375
no net on Top Overlay "TOPOVERLAY682" (solid, pour order 0): 257.423,178.125 cw(c261,173) 260.025,179.173 260.025,178.125
no net on Top Overlay "TOPOVERLAY683" (solid, pour order 0): 261.975,178.125 261.975,179.173 cw(c261,173) 264.577,178.125
no net on Top Overlay "TOPOVERLAY684" (solid, pour order 0): 257.423,118.125 cw(c261,113) 260.025,119.173 260.025,118.125
no net on Top Overlay "TOPOVERLAY685" (solid, pour order 0): 261.975,118.125 261.975,119.173 cw(c261,113) 264.577,118.125
no net on Top Overlay "TOPOVERLAY686" (solid, pour order 0): 261.975,125.375 264.577,125.375 cw(c261,130.5) 261.975,124.327
no net on Top Overlay "TOPOVERLAY687" (solid, pour order 0): 260.025,124.327 cw(c261,130.5) 257.423,125.375 260.025,125.375
no net on Bottom Overlay "BOTTOMOVERLAY688" (solid, pour order 0): 177.95,244.4 ccw(c178.2,244.4) 178.45,244.4 ccw(c178.2,244.4)
no net on Bottom Overlay "BOTTOMOVERLAY689" (solid, pour order 0): 177.95,234.4 ccw(c178.2,234.4) 178.45,234.4 ccw(c178.2,234.4)
no net on Bottom Overlay "BOTTOMOVERLAY690" (solid, pour order 0): 185.95,244.4 ccw(c186.2,244.4) 186.45,244.4 ccw(c186.2,244.4)
no net on Bottom Overlay "BOTTOMOVERLAY691" (solid, pour order 0): 186.25,235 ccw(c186.5,235) 186.75,235 ccw(c186.5,235)
no net on Bottom Overlay "BOTTOMOVERLAY692" (solid, pour order 0): 193.95,244.4 ccw(c194.2,244.4) 194.45,244.4 ccw(c194.2,244.4)
no net on Bottom Overlay "BOTTOMOVERLAY693" (solid, pour order 0): 194.25,235 ccw(c194.5,235) 194.75,235 ccw(c194.5,235)
no net on Bottom Overlay "BOTTOMOVERLAY694" (solid, pour order 0): 100.65,219.2 ccw(c100.9,219.2) 101.15,219.2 ccw(c100.9,219.2)
no net on Bottom Overlay "BOTTOMOVERLAY695" (solid, pour order 0): 103.65,219.2 ccw(c103.9,219.2) 104.15,219.2 ccw(c103.9,219.2)
no net on Bottom Overlay "BOTTOMOVERLAY696" (solid, pour order 0): 273.775,223.8 ccw(c274.025,223.8) 274.275,223.8 ccw(c274.025,223.8)
no net on Bottom Overlay "BOTTOMOVERLAY697" (solid, pour order 0): 122,212.5 ccw(c122.3,212.5) 122.6,212.5 ccw(c122.3,212.5)
no net on Bottom Overlay "BOTTOMOVERLAY698" (solid, pour order 0): 122,152.5 ccw(c122.3,152.5) 122.6,152.5 ccw(c122.3,152.5)
no net on Bottom Overlay "BOTTOMOVERLAY699" (solid, pour order 0): 273.775,163.8 ccw(c274.025,163.8) 274.275,163.8 ccw(c274.025,163.8)
no net on Bottom Overlay "BOTTOMOVERLAY700" (solid, pour order 0): 122,92.5 ccw(c122.3,92.5) 122.6,92.5 ccw(c122.3,92.5)
no net on Bottom Overlay "BOTTOMOVERLAY701" (solid, pour order 0): 273.775,103.8 ccw(c274.025,103.8) 274.275,103.8 ccw(c274.025,103.8)
no net on Bottom Overlay "BOTTOMOVERLAY702" (solid, pour order 0): 122,32.5 ccw(c122.3,32.5) 122.6,32.5 ccw(c122.3,32.5)
no net on Bottom Overlay "BOTTOMOVERLAY703" (solid, pour order 0): 273.775,43.8 ccw(c274.025,43.8) 274.275,43.8 ccw(c274.025,43.8)
no net on Bottom Overlay "BOTTOMOVERLAY704" (solid, pour order 0): 100.65,159.2 ccw(c100.9,159.2) 101.15,159.2 ccw(c100.9,159.2)
no net on Bottom Overlay "BOTTOMOVERLAY705" (solid, pour order 0): 103.65,159.2 ccw(c103.9,159.2) 104.15,159.2 ccw(c103.9,159.2)
no net on Bottom Overlay "BOTTOMOVERLAY706" (solid, pour order 0): 51.6,139.2 ccw(c51.85,139.2) 52.1,139.2 ccw(c51.85,139.2)
no net on Bottom Overlay "BOTTOMOVERLAY707" (solid, pour order 0): 51.6,132.7 ccw(c51.85,132.7) 52.1,132.7 ccw(c51.85,132.7)
no net on Bottom Overlay "BOTTOMOVERLAY708" (solid, pour order 0): 177.95,124.4 ccw(c178.2,124.4) 178.45,124.4 ccw(c178.2,124.4)
no net on Bottom Overlay "BOTTOMOVERLAY709" (solid, pour order 0): 185.95,124.4 ccw(c186.2,124.4) 186.45,124.4 ccw(c186.2,124.4)
no net on Bottom Overlay "BOTTOMOVERLAY710" (solid, pour order 0): 193.95,124.4 ccw(c194.2,124.4) 194.45,124.4 ccw(c194.2,124.4)
no net on Bottom Overlay "BOTTOMOVERLAY711" (solid, pour order 0): 177.95,114.4 ccw(c178.2,114.4) 178.45,114.4 ccw(c178.2,114.4)
no net on Bottom Overlay "BOTTOMOVERLAY712" (solid, pour order 0): 186.25,115 ccw(c186.5,115) 186.75,115 ccw(c186.5,115)
no net on Bottom Overlay "BOTTOMOVERLAY713" (solid, pour order 0): 194.25,115 ccw(c194.5,115) 194.75,115 ccw(c194.5,115)
no net on Bottom Overlay "BOTTOMOVERLAY714" (solid, pour order 0): 100.65,99.2 ccw(c100.9,99.2) 101.15,99.2 ccw(c100.9,99.2)
no net on Bottom Overlay "BOTTOMOVERLAY715" (solid, pour order 0): 103.65,99.2 ccw(c103.9,99.2) 104.15,99.2 ccw(c103.9,99.2)
no net on Bottom Overlay "BOTTOMOVERLAY716" (solid, pour order 0): 51.6,79.2 ccw(c51.85,79.2) 52.1,79.2 ccw(c51.85,79.2)
no net on Bottom Overlay "BOTTOMOVERLAY717" (solid, pour order 0): 51.6,72.7 ccw(c51.85,72.7) 52.1,72.7 ccw(c51.85,72.7)
no net on Bottom Overlay "BOTTOMOVERLAY718" (solid, pour order 0): 177.95,64.4 ccw(c178.2,64.4) 178.45,64.4 ccw(c178.2,64.4)
no net on Bottom Overlay "BOTTOMOVERLAY719" (solid, pour order 0): 185.95,64.4 ccw(c186.2,64.4) 186.45,64.4 ccw(c186.2,64.4)
no net on Bottom Overlay "BOTTOMOVERLAY720" (solid, pour order 0): 193.95,64.4 ccw(c194.2,64.4) 194.45,64.4 ccw(c194.2,64.4)
no net on Bottom Overlay "BOTTOMOVERLAY721" (solid, pour order 0): 177.95,54.4 ccw(c178.2,54.4) 178.45,54.4 ccw(c178.2,54.4)
no net on Bottom Overlay "BOTTOMOVERLAY722" (solid, pour order 0): 186.25,55 ccw(c186.5,55) 186.75,55 ccw(c186.5,55)
no net on Bottom Overlay "BOTTOMOVERLAY723" (solid, pour order 0): 194.25,55 ccw(c194.5,55) 194.75,55 ccw(c194.5,55)
no net on Bottom Overlay "BOTTOMOVERLAY724" (solid, pour order 0): 100.65,39.2 ccw(c100.9,39.2) 101.15,39.2 ccw(c100.9,39.2)
no net on Bottom Overlay "BOTTOMOVERLAY725" (solid, pour order 0): 103.65,39.2 ccw(c103.9,39.2) 104.15,39.2 ccw(c103.9,39.2)
no net on Bottom Overlay "BOTTOMOVERLAY726" (solid, pour order 0): 51.6,259.2 ccw(c51.85,259.2) 52.1,259.2 ccw(c51.85,259.2)
no net on Bottom Overlay "BOTTOMOVERLAY727" (solid, pour order 0): 51.6,252.7 ccw(c51.85,252.7) 52.1,252.7 ccw(c51.85,252.7)
no net on Bottom Overlay "BOTTOMOVERLAY728" (solid, pour order 0): 51.6,199.2 ccw(c51.85,199.2) 52.1,199.2 ccw(c51.85,199.2)
no net on Bottom Overlay "BOTTOMOVERLAY729" (solid, pour order 0): 51.6,192.7 ccw(c51.85,192.7) 52.1,192.7 ccw(c51.85,192.7)
no net on Bottom Overlay "BOTTOMOVERLAY730" (solid, pour order 0): 177.95,184.4 ccw(c178.2,184.4) 178.45,184.4 ccw(c178.2,184.4)
no net on Bottom Overlay "BOTTOMOVERLAY731" (solid, pour order 0): 185.95,184.4 ccw(c186.2,184.4) 186.45,184.4 ccw(c186.2,184.4)
no net on Bottom Overlay "BOTTOMOVERLAY732" (solid, pour order 0): 193.95,184.4 ccw(c194.2,184.4) 194.45,184.4 ccw(c194.2,184.4)
no net on Bottom Overlay "BOTTOMOVERLAY733" (solid, pour order 0): 177.95,174.4 ccw(c178.2,174.4) 178.45,174.4 ccw(c178.2,174.4)
no net on Bottom Overlay "BOTTOMOVERLAY734" (solid, pour order 0): 186.25,175 ccw(c186.5,175) 186.75,175 ccw(c186.5,175)
no net on Bottom Overlay "BOTTOMOVERLAY735" (solid, pour order 0): 194.25,175 ccw(c194.5,175) 194.75,175 ccw(c194.5,175)
no net on Bottom Overlay "BOTTOMOVERLAY736" (solid, pour order 0): 275.1,238.075 275.1,238.75 276.4,238.75 276.4,238.075 276.15,238.075 276.15,238.5 275.35,238.5 275.35,238.075
no net on Bottom Overlay "BOTTOMOVERLAY737" (solid, pour order 0): 276.075,235.1 276.075,235.35 276.5,235.35 276.5,236.15 276.075,236.15 276.075,236.4 276.75,236.4 276.75,235.1
no net on Bottom Overlay "BOTTOMOVERLAY738" (solid, pour order 0): 275.1,178.075 275.1,178.75 276.4,178.75 276.4,178.075 276.15,178.075 276.15,178.5 275.35,178.5 275.35,178.075
no net on Bottom Overlay "BOTTOMOVERLAY739" (solid, pour order 0): 276.075,175.1 276.075,175.35 276.5,175.35 276.5,176.15 276.075,176.15 276.075,176.4 276.75,176.4 276.75,175.1
no net on Bottom Overlay "BOTTOMOVERLAY740" (solid, pour order 0): 275.1,118.075 275.1,118.75 276.4,118.75 276.4,118.075 276.15,118.075 276.15,118.5 275.35,118.5 275.35,118.075
no net on Bottom Overlay "BOTTOMOVERLAY741" (solid, pour order 0): 276.075,115.1 276.075,115.35 276.5,115.35 276.5,116.15 276.075,116.15 276.075,116.4 276.75,116.4 276.75,115.1
no net on Bottom Overlay "BOTTOMOVERLAY742" (solid, pour order 0): 275.1,58.075 275.1,58.75 276.4,58.75 276.4,58.075 276.15,58.075 276.15,58.5 275.35,58.5 275.35,58.075
no net on Bottom Overlay "BOTTOMOVERLAY743" (solid, pour order 0): 276.075,55.1 276.075,55.35 276.5,55.35 276.5,56.15 276.075,56.15 276.075,56.4 276.75,56.4 276.75,55.1
no net on Bottom Overlay "BOTTOMOVERLAY744" (solid, pour order 0): 97.75,210.35 ccw(c98,210.35) 98.25,210.35 ccw(c98,210.35)
no net on Bottom Overlay "BOTTOMOVERLAY745" (solid, pour order 0): 89.9,217 ccw(c90.15,217) 90.4,217 ccw(c90.15,217)
no net on Bottom Overlay "BOTTOMOVERLAY746" (solid, pour order 0): 102.75,210.35 ccw(c103,210.35) 103.25,210.35 ccw(c103,210.35)
no net on Bottom Overlay "BOTTOMOVERLAY747" (solid, pour order 0): 107.75,210.35 ccw(c108,210.35) 108.25,210.35 ccw(c108,210.35)
no net on Bottom Overlay "BOTTOMOVERLAY748" (solid, pour order 0): 279.6,211.25 ccw(c279.85,211.25) 280.1,211.25 ccw(c279.85,211.25)
no net on Bottom Overlay "BOTTOMOVERLAY749" (solid, pour order 0): 271.6,211.25 ccw(c271.85,211.25) 272.1,211.25 ccw(c271.85,211.25)
no net on Bottom Overlay "BOTTOMOVERLAY750" (solid, pour order 0): 272.9,216.75 ccw(c273.15,216.75) 273.4,216.75 ccw(c273.15,216.75)
no net on Bottom Overlay "BOTTOMOVERLAY751" (solid, pour order 0): 97.75,150.35 ccw(c98,150.35) 98.25,150.35 ccw(c98,150.35)
no net on Bottom Overlay "BOTTOMOVERLAY752" (solid, pour order 0): 89.9,157 ccw(c90.15,157) 90.4,157 ccw(c90.15,157)
no net on Bottom Overlay "BOTTOMOVERLAY753" (solid, pour order 0): 102.75,150.35 ccw(c103,150.35) 103.25,150.35 ccw(c103,150.35)
no net on Bottom Overlay "BOTTOMOVERLAY754" (solid, pour order 0): 107.75,150.35 ccw(c108,150.35) 108.25,150.35 ccw(c108,150.35)
no net on Bottom Overlay "BOTTOMOVERLAY755" (solid, pour order 0): 279.6,151.25 ccw(c279.85,151.25) 280.1,151.25 ccw(c279.85,151.25)
no net on Bottom Overlay "BOTTOMOVERLAY756" (solid, pour order 0): 271.6,151.25 ccw(c271.85,151.25) 272.1,151.25 ccw(c271.85,151.25)
no net on Bottom Overlay "BOTTOMOVERLAY757" (solid, pour order 0): 272.9,156.75 ccw(c273.15,156.75) 273.4,156.75 ccw(c273.15,156.75)
no net on Bottom Overlay "BOTTOMOVERLAY758" (solid, pour order 0): 97.75,90.35 ccw(c98,90.35) 98.25,90.35 ccw(c98,90.35)
no net on Bottom Overlay "BOTTOMOVERLAY759" (solid, pour order 0): 89.9,97 ccw(c90.15,97) 90.4,97 ccw(c90.15,97)
no net on Bottom Overlay "BOTTOMOVERLAY760" (solid, pour order 0): 102.75,90.35 ccw(c103,90.35) 103.25,90.35 ccw(c103,90.35)
no net on Bottom Overlay "BOTTOMOVERLAY761" (solid, pour order 0): 107.75,90.35 ccw(c108,90.35) 108.25,90.35 ccw(c108,90.35)
no net on Bottom Overlay "BOTTOMOVERLAY762" (solid, pour order 0): 279.6,91.25 ccw(c279.85,91.25) 280.1,91.25 ccw(c279.85,91.25)
no net on Bottom Overlay "BOTTOMOVERLAY763" (solid, pour order 0): 271.6,91.25 ccw(c271.85,91.25) 272.1,91.25 ccw(c271.85,91.25)
no net on Bottom Overlay "BOTTOMOVERLAY764" (solid, pour order 0): 272.9,96.75 ccw(c273.15,96.75) 273.4,96.75 ccw(c273.15,96.75)
no net on Bottom Overlay "BOTTOMOVERLAY765" (solid, pour order 0): 97.75,30.35 ccw(c98,30.35) 98.25,30.35 ccw(c98,30.35)
no net on Bottom Overlay "BOTTOMOVERLAY766" (solid, pour order 0): 89.9,37 ccw(c90.15,37) 90.4,37 ccw(c90.15,37)
no net on Bottom Overlay "BOTTOMOVERLAY767" (solid, pour order 0): 102.75,30.35 ccw(c103,30.35) 103.25,30.35 ccw(c103,30.35)
no net on Bottom Overlay "BOTTOMOVERLAY768" (solid, pour order 0): 107.75,30.35 ccw(c108,30.35) 108.25,30.35 ccw(c108,30.35)
no net on Bottom Overlay "BOTTOMOVERLAY769" (solid, pour order 0): 279.6,31.25 ccw(c279.85,31.25) 280.1,31.25 ccw(c279.85,31.25)
no net on Bottom Overlay "BOTTOMOVERLAY770" (solid, pour order 0): 271.6,31.25 ccw(c271.85,31.25) 272.1,31.25 ccw(c271.85,31.25)
no net on Bottom Overlay "BOTTOMOVERLAY771" (solid, pour order 0): 272.9,36.75 ccw(c273.15,36.75) 273.4,36.75 ccw(c273.15,36.75)
no net on Bottom Overlay "BOTTOMOVERLAY772" (solid, pour order 0): 108.45,207.1 ccw(c108.7,207.1) 108.95,207.1 ccw(c108.7,207.1)
no net on Bottom Overlay "BOTTOMOVERLAY773" (solid, pour order 0): 278.05,207.65 ccw(c278.3,207.65) 278.55,207.65 ccw(c278.3,207.65)
no net on Bottom Overlay "BOTTOMOVERLAY774" (solid, pour order 0): 281.4,236.95 ccw(c281.65,236.95) 281.9,236.95 ccw(c281.65,236.95)
no net on Bottom Overlay "BOTTOMOVERLAY775" (solid, pour order 0): 108.45,147.1 ccw(c108.7,147.1) 108.95,147.1 ccw(c108.7,147.1)
no net on Bottom Overlay "BOTTOMOVERLAY776" (solid, pour order 0): 278.05,147.65 ccw(c278.3,147.65) 278.55,147.65 ccw(c278.3,147.65)
no net on Bottom Overlay "BOTTOMOVERLAY777" (solid, pour order 0): 281.4,176.95 ccw(c281.65,176.95) 281.9,176.95 ccw(c281.65,176.95)
no net on Bottom Overlay "BOTTOMOVERLAY778" (solid, pour order 0): 108.45,87.1 ccw(c108.7,87.1) 108.95,87.1 ccw(c108.7,87.1)
no net on Bottom Overlay "BOTTOMOVERLAY779" (solid, pour order 0): 278.05,87.65 ccw(c278.3,87.65) 278.55,87.65 ccw(c278.3,87.65)
no net on Bottom Overlay "BOTTOMOVERLAY780" (solid, pour order 0): 281.4,116.95 ccw(c281.65,116.95) 281.9,116.95 ccw(c281.65,116.95)
no net on Bottom Overlay "BOTTOMOVERLAY781" (solid, pour order 0): 108.45,27.1 ccw(c108.7,27.1) 108.95,27.1 ccw(c108.7,27.1)
no net on Bottom Overlay "BOTTOMOVERLAY782" (solid, pour order 0): 278.05,27.65 ccw(c278.3,27.65) 278.55,27.65 ccw(c278.3,27.65)
no net on Bottom Overlay "BOTTOMOVERLAY783" (solid, pour order 0): 281.4,56.95 ccw(c281.65,56.95) 281.9,56.95 ccw(c281.65,56.95)
no net on Bottom Overlay "BOTTOMOVERLAY784" (solid, pour order 0): 275.1,221.35 275.1,221.85 275.6,221.85 275.6,221.5 276.4,221.5 276.4,221.85 276.9,221.85 276.9,221.35
no net on Bottom Overlay "BOTTOMOVERLAY785" (solid, pour order 0): 277.6,221.35 277.6,221.85 278.1,221.85 278.1,221.5 278.9,221.5 278.9,221.85 279.4,221.85 279.4,221.35
no net on Bottom Overlay "BOTTOMOVERLAY786" (solid, pour order 0): 280.35,221.35 280.35,221.85 280.85,221.85 280.85,221.5 281.65,221.5 281.65,221.85 282.15,221.85 282.15,221.35
no net on Bottom Overlay "BOTTOMOVERLAY787" (solid, pour order 0): 275.1,161.35 275.1,161.85 275.6,161.85 275.6,161.5 276.4,161.5 276.4,161.85 276.9,161.85 276.9,161.35
no net on Bottom Overlay "BOTTOMOVERLAY788" (solid, pour order 0): 277.6,161.35 277.6,161.85 278.1,161.85 278.1,161.5 278.9,161.5 278.9,161.85 279.4,161.85 279.4,161.35
no net on Bottom Overlay "BOTTOMOVERLAY789" (solid, pour order 0): 280.35,161.35 280.35,161.85 280.85,161.85 280.85,161.5 281.65,161.5 281.65,161.85 282.15,161.85 282.15,161.35
no net on Bottom Overlay "BOTTOMOVERLAY790" (solid, pour order 0): 275.1,101.35 275.1,101.85 275.6,101.85 275.6,101.5 276.4,101.5 276.4,101.85 276.9,101.85 276.9,101.35
no net on Bottom Overlay "BOTTOMOVERLAY791" (solid, pour order 0): 277.6,101.35 277.6,101.85 278.1,101.85 278.1,101.5 278.9,101.5 278.9,101.85 279.4,101.85 279.4,101.35
no net on Bottom Overlay "BOTTOMOVERLAY792" (solid, pour order 0): 280.35,101.35 280.35,101.85 280.85,101.85 280.85,101.5 281.65,101.5 281.65,101.85 282.15,101.85 282.15,101.35
no net on Bottom Overlay "BOTTOMOVERLAY793" (solid, pour order 0): 275.1,41.35 275.1,41.85 275.6,41.85 275.6,41.5 276.4,41.5 276.4,41.85 276.9,41.85 276.9,41.35
no net on Bottom Overlay "BOTTOMOVERLAY794" (solid, pour order 0): 277.6,41.35 277.6,41.85 278.1,41.85 278.1,41.5 278.9,41.5 278.9,41.85 279.4,41.85 279.4,41.35
no net on Bottom Overlay "BOTTOMOVERLAY795" (solid, pour order 0): 280.35,41.35 280.35,41.85 280.85,41.85 280.85,41.5 281.65,41.5 281.65,41.85 282.15,41.85 282.15,41.35
no net on Bottom Overlay "BOTTOMOVERLAY796" (solid, pour order 0): 272.6,58.15 272.6,58.65 274.4,58.65 274.4,58.15 273.9,58.15 273.9,58.5 273.1,58.5 273.1,58.15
